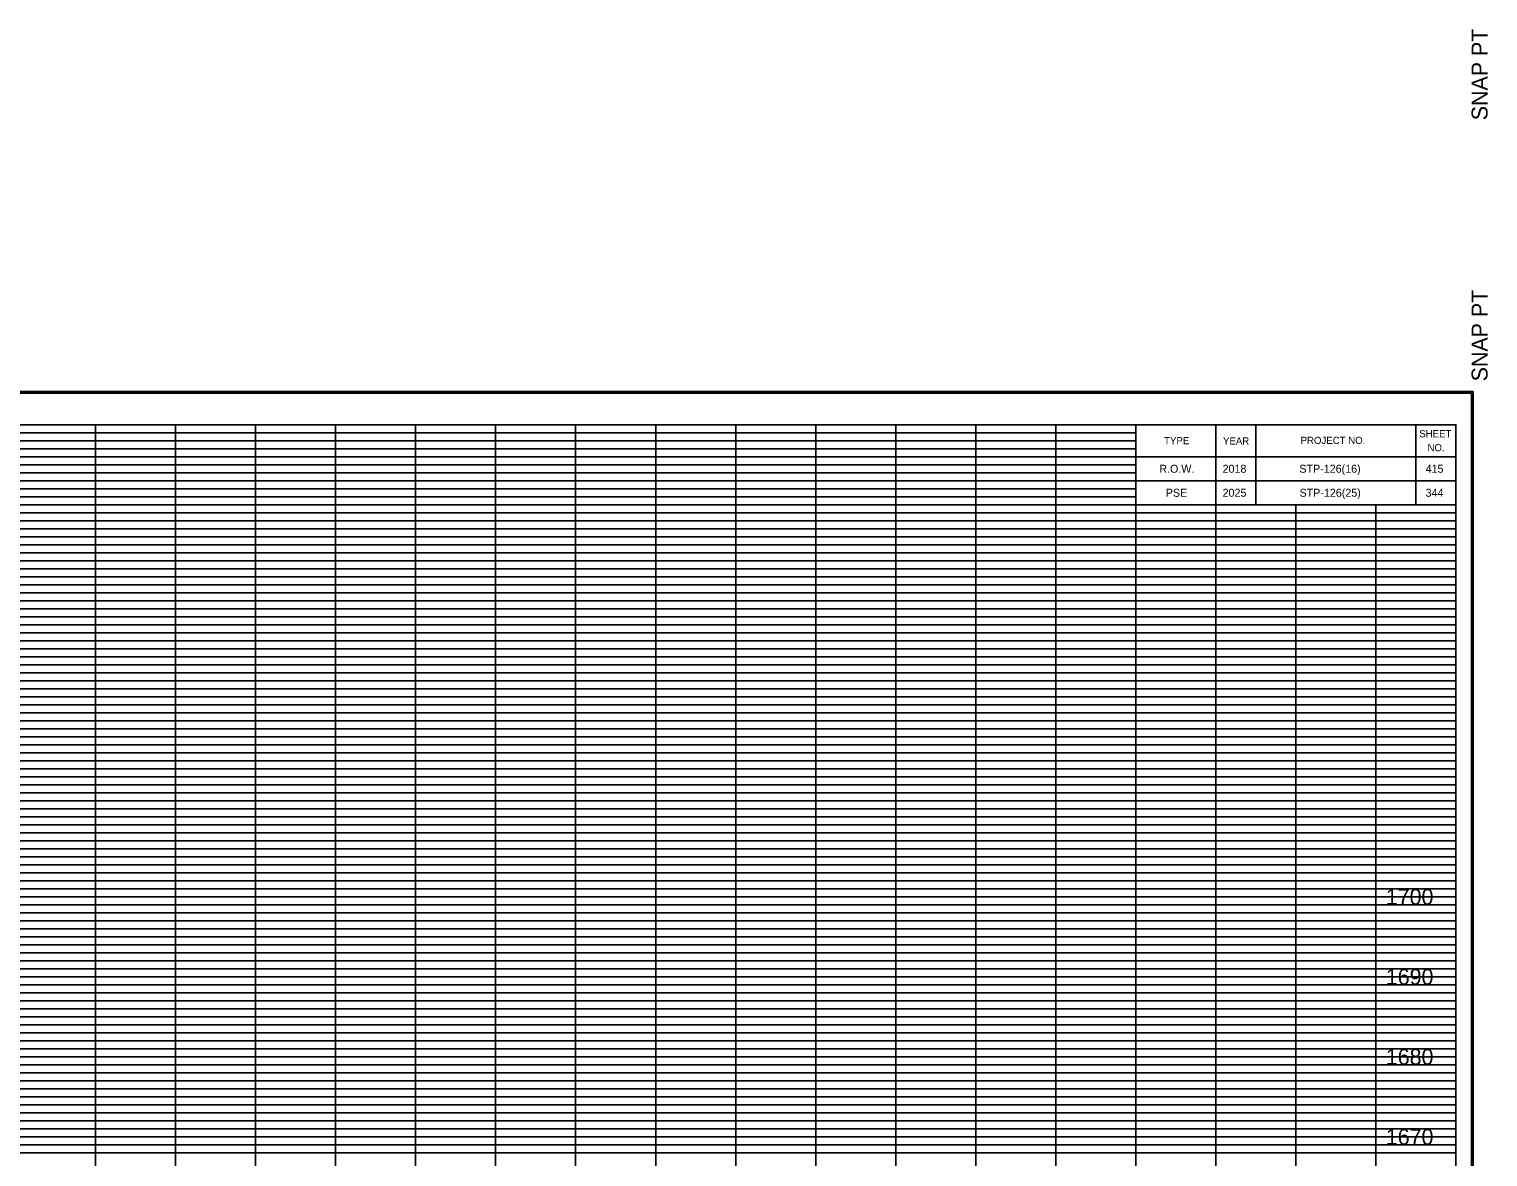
# Model space of a CAD drawing. Extents: x 980 to 2228, y 978 to 2394.
# Drawn here: x 1141.7 to 1324, y 1118.5 to 1259.4 of the extents above; entities that cross this region are included whole.
import ezdxf

# ---------------------------------------------------------------- set-up
doc = ezdxf.new("R2010")
doc.units = 0
for name, color, linetype in [('DESIGN - SCRATCH - User 1', 7, 'Continuous'), ('DESIGN - SHEET - Corner Text', 7, 'Continuous'), ('DESIGN - SHEET - Light Grid', 7, 'Continuous'), ('DESIGN - SHEET - Linework', 7, 'Continuous'), ('DESIGN - SHEET - Plot Shape', 7, 'Continuous'), ('DESIGN - TYPICAL - Finished Grade and Subgrade', 7, 'Continuous')]:
    doc.layers.add(name, color=color, linetype=linetype)

# ---------------------------------------------------------------- blocks, each defined once
blk = doc.blocks.new('XSTSHT')
at = {"layer": 'DESIGN - SCRATCH - User 1'}
for p, q in [((28.5, 20.45), (28.5, 20.45)), ((29.24, 20.45), (29.24, 20.45)), ((30.49, 20.45), (30.49, 20.45)), ((31.74, 20.45), (31.74, 20.45)), ((28.5, 20.15), (28.5, 20.15)), ((29.24, 20.15), (29.24, 20.15)), ((30.49, 20.15), (30.49, 20.15)), ((31.74, 20.15), (31.74, 20.15))]:
    blk.add_line(p, q, dxfattribs=at)
at = {"layer": 'DESIGN - SHEET - Light Grid'}
for p, q in [((8, 20.9), (16, 20.9)), ((8, 20.8), (16, 20.8)), ((16, 20.9), (24, 20.9)), ((16, 20.8), (24, 20.8)), ((24, 20.9), (28, 20.9)), ((24, 20.8), (28, 20.8)), ((8, 20.7), (16, 20.7)), ((8, 20.6), (16, 20.6)), ((16, 20.7), (24, 20.7)), ((16, 20.6), (24, 20.6)), ((24, 20.7), (28, 20.7)), ((24, 20.6), (28, 20.6)), ((8, 20.5), (16, 20.5)), ((16, 20.5), (24, 20.5)), ((24, 20.5), (28, 20.5)), ((8, 20.4), (16, 20.4)), ((8, 20.3), (16, 20.3)), ((16, 20.4), (24, 20.4)), ((16, 20.3), (24, 20.3)), ((24, 20.4), (28, 20.4)), ((24, 20.3), (28, 20.3)), ((8, 20.2), (16, 20.2)), ((8, 20.1), (16, 20.1)), ((16, 20.2), (24, 20.2)), ((16, 20.1), (24, 20.1)), ((24, 20.2), (28, 20.2)), ((24, 20.1), (28, 20.1)), ((8, 19.9), (16, 19.9)), ((16, 19.9), (24, 19.9)), ((24, 19.9), (32, 19.9)), ((8, 19.8), (16, 19.8)), ((8, 19.7), (16, 19.7)), ((16, 19.8), (24, 19.8)), ((16, 19.7), (24, 19.7)), ((24, 19.8), (32, 19.8)), ((24, 19.7), (32, 19.7)), ((8, 19.6), (16, 19.6)), ((16, 19.6), (24, 19.6)), ((24, 19.6), (32, 19.6)), ((8, 19.5), (16, 19.5)), ((8, 19.4), (16, 19.4)), ((16, 19.5), (24, 19.5)), ((16, 19.4), (24, 19.4)), ((24, 19.5), (32, 19.5)), ((24, 19.4), (32, 19.4)), ((8, 19.3), (16, 19.3)), ((8, 19.2), (16, 19.2)), ((16, 19.3), (24, 19.3)), ((16, 19.2), (24, 19.2)), ((24, 19.3), (32, 19.3)), ((24, 19.2), (32, 19.2)), ((8, 19.1), (16, 19.1)), ((16, 19.1), (24, 19.1)), ((24, 19.1), (32, 19.1)), ((8, 18.9), (16, 18.9)), ((8, 18.8), (16, 18.8)), ((16, 18.9), (24, 18.9)), ((16, 18.8), (24, 18.8)), ((24, 18.9), (32, 18.9)), ((24, 18.8), (32, 18.8)), ((8, 18.7), (16, 18.7)), ((8, 18.6), (16, 18.6)), ((16, 18.7), (24, 18.7)), ((16, 18.6), (24, 18.6)), ((24, 18.7), (32, 18.7)), ((24, 18.6), (32, 18.6)), ((8, 18.5), (16, 18.5)), ((16, 18.5), (24, 18.5)), ((24, 18.5), (32, 18.5)), ((8, 18.4), (16, 18.4)), ((8, 18.3), (16, 18.3)), ((16, 18.4), (24, 18.4)), ((16, 18.3), (24, 18.3)), ((24, 18.4), (32, 18.4)), ((24, 18.3), (32, 18.3)), ((8, 18.2), (16, 18.2)), ((8, 18.1), (16, 18.1)), ((16, 18.2), (24, 18.2)), ((16, 18.1), (24, 18.1)), ((24, 18.2), (32, 18.2)), ((24, 18.1), (32, 18.1)), ((8, 17.9), (16, 17.9)), ((16, 17.9), (24, 17.9)), ((24, 17.9), (32, 17.9)), ((8, 17.8), (16, 17.8)), ((8, 17.7), (16, 17.7)), ((16, 17.8), (24, 17.8)), ((16, 17.7), (24, 17.7)), ((24, 17.8), (32, 17.8)), ((24, 17.7), (32, 17.7)), ((8, 17.6), (16, 17.6)), ((16, 17.6), (24, 17.6)), ((24, 17.6), (32, 17.6)), ((8, 17.5), (16, 17.5)), ((8, 17.4), (16, 17.4)), ((16, 17.5), (24, 17.5)), ((16, 17.4), (24, 17.4)), ((24, 17.5), (32, 17.5)), ((24, 17.4), (32, 17.4)), ((8, 17.3), (16, 17.3)), ((8, 17.2), (16, 17.2)), ((16, 17.3), (24, 17.3)), ((16, 17.2), (24, 17.2)), ((24, 17.3), (32, 17.3)), ((24, 17.2), (32, 17.2)), ((8, 17.1), (16, 17.1)), ((16, 17.1), (24, 17.1)), ((24, 17.1), (32, 17.1)), ((8, 16.9), (16, 16.9)), ((8, 16.8), (16, 16.8)), ((16, 16.9), (24, 16.9)), ((16, 16.8), (24, 16.8)), ((24, 16.9), (32, 16.9)), ((24, 16.8), (32, 16.8)), ((8, 16.7), (16, 16.7)), ((8, 16.6), (16, 16.6)), ((16, 16.7), (24, 16.7)), ((16, 16.6), (24, 16.6)), ((24, 16.7), (32, 16.7)), ((24, 16.6), (32, 16.6)), ((8, 16.5), (16, 16.5)), ((16, 16.5), (24, 16.5)), ((24, 16.5), (32, 16.5)), ((8, 16.4), (16, 16.4)), ((8, 16.3), (16, 16.3)), ((16, 16.4), (24, 16.4)), ((16, 16.3), (24, 16.3)), ((24, 16.4), (32, 16.4)), ((24, 16.3), (32, 16.3)), ((8, 16.2), (16, 16.2)), ((8, 16.1), (16, 16.1)), ((16, 16.2), (24, 16.2)), ((16, 16.1), (24, 16.1)), ((24, 16.2), (32, 16.2)), ((24, 16.1), (32, 16.1)), ((8, 15.9), (16, 15.9)), ((16, 15.9), (24, 15.9)), ((24, 15.9), (32, 15.9)), ((8, 15.8), (16, 15.8)), ((8, 15.7), (16, 15.7)), ((16, 15.8), (24, 15.8)), ((16, 15.7), (24, 15.7)), ((24, 15.8), (32, 15.8)), ((24, 15.7), (32, 15.7)), ((8, 15.6), (16, 15.6)), ((8, 15.5), (16, 15.5)), ((16, 15.6), (24, 15.6)), ((16, 15.5), (24, 15.5)), ((24, 15.6), (32, 15.6)), ((24, 15.5), (32, 15.5)), ((8, 15.4), (16, 15.4)), ((16, 15.4), (24, 15.4)), ((24, 15.4), (32, 15.4)), ((8, 15.3), (16, 15.3)), ((8, 15.2), (16, 15.2)), ((16, 15.3), (24, 15.3)), ((16, 15.2), (24, 15.2)), ((24, 15.3), (32, 15.3)), ((24, 15.2), (32, 15.2)), ((8, 15.1), (16, 15.1)), ((16, 15.1), (24, 15.1)), ((24, 15.1), (32, 15.1)), ((8, 14.9), (16, 14.9)), ((8, 14.8), (16, 14.8)), ((16, 14.9), (24, 14.9)), ((16, 14.8), (24, 14.8)), ((24, 14.9), (32, 14.9)), ((24, 14.8), (32, 14.8)), ((8, 14.7), (16, 14.7)), ((8, 14.6), (16, 14.6)), ((16, 14.7), (24, 14.7)), ((16, 14.6), (24, 14.6)), ((24, 14.7), (32, 14.7)), ((24, 14.6), (32, 14.6)), ((8, 14.5), (16, 14.5)), ((16, 14.5), (24, 14.5)), ((24, 14.5), (32, 14.5)), ((8, 14.4), (16, 14.4)), ((8, 14.3), (16, 14.3)), ((16, 14.4), (24, 14.4)), ((16, 14.3), (24, 14.3)), ((24, 14.4), (32, 14.4)), ((24, 14.3), (32, 14.3)), ((8, 14.2), (16, 14.2)), ((8, 14.1), (16, 14.1)), ((16, 14.2), (24, 14.2)), ((16, 14.1), (24, 14.1)), ((24, 14.2), (32, 14.2)), ((24, 14.1), (32, 14.1)), ((8, 13.9), (16, 13.9)), ((16, 13.9), (24, 13.9)), ((24, 13.9), (32, 13.9)), ((8, 13.8), (16, 13.8)), ((8, 13.7), (16, 13.7)), ((16, 13.8), (24, 13.8)), ((16, 13.7), (24, 13.7)), ((24, 13.8), (32, 13.8)), ((24, 13.7), (32, 13.7)), ((8, 13.6), (16, 13.6)), ((8, 13.5), (16, 13.5)), ((16, 13.6), (24, 13.6)), ((16, 13.5), (24, 13.5)), ((24, 13.6), (32, 13.6)), ((24, 13.5), (32, 13.5)), ((8, 13.4), (16, 13.4)), ((16, 13.4), (24, 13.4)), ((24, 13.4), (32, 13.4)), ((8, 13.3), (16, 13.3)), ((8, 13.2), (16, 13.2)), ((16, 13.3), (24, 13.3)), ((16, 13.2), (24, 13.2)), ((24, 13.3), (32, 13.3)), ((24, 13.2), (32, 13.2)), ((8, 13.1), (16, 13.1)), ((16, 13.1), (24, 13.1)), ((24, 13.1), (32, 13.1)), ((8, 12.9), (16, 12.9)), ((8, 12.8), (16, 12.8)), ((16, 12.9), (24, 12.9)), ((16, 12.8), (24, 12.8)), ((24, 12.9), (32, 12.9)), ((24, 12.8), (32, 12.8)), ((8, 12.7), (16, 12.7)), ((8, 12.6), (16, 12.6)), ((16, 12.7), (24, 12.7)), ((16, 12.6), (24, 12.6)), ((24, 12.7), (32, 12.7)), ((24, 12.6), (32, 12.6)), ((8, 12.5), (16, 12.5)), ((8, 12.4), (16, 12.4)), ((16, 12.5), (24, 12.5)), ((16, 12.4), (24, 12.4)), ((24, 12.5), (32, 12.5)), ((24, 12.4), (32, 12.4)), ((8, 12.3), (16, 12.3)), ((16, 12.3), (24, 12.3)), ((24, 12.3), (32, 12.3)), ((8, 12.2), (16, 12.2)), ((8, 12.1), (16, 12.1)), ((16, 12.2), (24, 12.2)), ((16, 12.1), (24, 12.1)), ((24, 12.2), (32, 12.2)), ((24, 12.1), (32, 12.1)), ((8, 11.9), (16, 11.9)), ((16, 11.9), (24, 11.9)), ((24, 11.9), (32, 11.9))]:
    blk.add_line(p, q, dxfattribs=at)
at = {"layer": 'DESIGN - SHEET - Linework'}
for p, q in [((-1.823, 21.414), (32.217, 21.414)), ((32.217, 21.414), (32.217, -0.414)), ((15, 0), (15, 21)), ((16, 0), (16, 21)), ((17, 0), (17, 21)), ((18, 0), (18, 21)), ((19, 0), (19, 21)), ((20, 0), (20, 21)), ((21, 0), (21, 21)), ((22, 0), (22, 21)), ((23, 0), (23, 21)), ((24, 0), (24, 21)), ((25, 0), (25, 21)), ((26, 0), (26, 21)), ((27, 0), (27, 21)), ((0, 20), (28, 20)), ((28, 0), (28, 20)), ((29, 0), (29, 20)), ((30, 0), (30, 20)), ((31, 0), (31, 20)), ((0, 19), (32, 19)), ((0, 18), (32, 18)), ((0, 17), (32, 17)), ((0, 16), (32, 16)), ((0, 15), (32, 15)), ((0, 14), (32, 14)), ((0, 13), (32, 13)), ((0, 12), (32, 12))]:
    blk.add_line(p, q, dxfattribs=at)
for points in [[(0, 21), (0, 0), (32, 0), (32, 21), (0, 21)], [(28, 21), (28, 20), (32, 20), (32, 21), (31.5, 21), (31.5, 20), (29.5, 20), (29.5, 21), (29, 21), (29, 20), (32, 20), (28, 20), (28, 20.3), (32, 20.3), (32, 20.6), (28, 20.6)]]:
    blk.add_lwpolyline(points, dxfattribs=at)
at = {"layer": 'DESIGN - SHEET - Plot Shape'}
for points in [[(-1.803, 21.394), (32.197, 21.394), (32.197, -0.394), (-1.803, -0.394)], [(-0.85, 21), (32, 21), (32, -0.25), (-0.85, -0.25)]]:
    blk.add_lwpolyline(points, close=True, dxfattribs=at)
at = {"layer": 'DESIGN - SHEET - Corner Text'}
for s, p in [('  SNAP PT', (32.397, 21.394)), ('SNAP PT  ', (32.397, -2.194))]:
    blk.add_text(s, height=0.2, rotation=90, dxfattribs=at).set_placement(p)
for s, p in [('TYPE', (28.354, 20.756)), ('YEAR', (29.09, 20.752)), ('PROJECT NO.', (30.06, 20.76)), ('SHEET', (31.543, 20.843)), ('NO.', (31.646, 20.669))]:
    blk.add_text(s, height=0.09, dxfattribs=at).set_placement(p)

msp = doc.modelspace()

# ---------------------------------------------------------------- linework, layer by layer
at = {"layer": 'DESIGN - SHEET - Plot Shape'}
msp.add_lwpolyline([(991.5, 1210), (1320, 1210), (1320, 997.5), (991.5, 997.5)], close=True, dxfattribs=at)

# ---------------------------------------------------------------- block references
at = {"layer": 'DESIGN - TYPICAL - Finished Grade and Subgrade', "xscale": 10, "yscale": 10}
for p in [(1000, 1270), (1000, 1000)]:
    msp.add_blockref('XSTSHT', p, dxfattribs=at)

# ---------------------------------------------------------------- texts
at = {"layer": 'DESIGN - SHEET - Corner Text'}
for s, height, p in [('R.O.W.', 1, (1282.94, 1204)), ('2018', 1, (1290.85, 1204)), ('STP-126(16)', 1, (1300.45, 1204)), ('415', 1, (1316.22, 1204)), ('PSE', 1, (1283.75, 1201)), ('2025', 1, (1290.85, 1201)), ('STP-126(25)', 1, (1300.47, 1201)), ('344', 1, (1316.22, 1201)), ('1700', 2, (1311.25, 1150)), ('1690', 2, (1311.25, 1140)), ('1680', 2, (1311.25, 1130)), ('1670', 2, (1311.25, 1120))]:
    msp.add_text(s, height=height, dxfattribs=at).set_placement(p)

doc.saveas('drawing.dxf')
